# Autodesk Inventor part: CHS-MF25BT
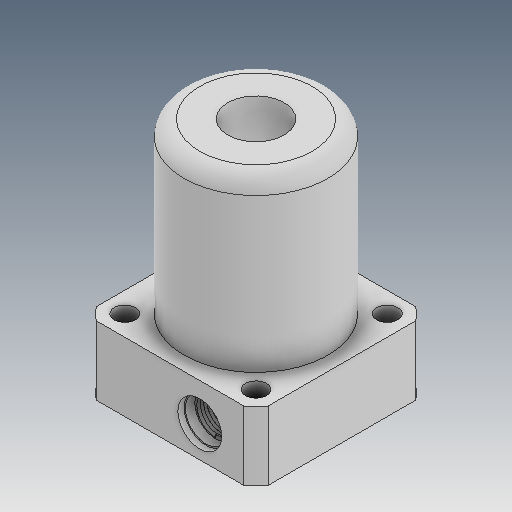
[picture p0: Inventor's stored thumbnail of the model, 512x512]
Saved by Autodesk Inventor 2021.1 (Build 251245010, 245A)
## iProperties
Created: 2019-04
Part Number: CHS-MF25BT
Material: Ogólny
Document SubType Name: Modeling
Designer: user
Density: 1 g/cm^3
Appearance: Domyślna
Author: user
Revision Number: ÈÎºÎ
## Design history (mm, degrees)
feature "ÊäÈë1"
node "Bryła1"
